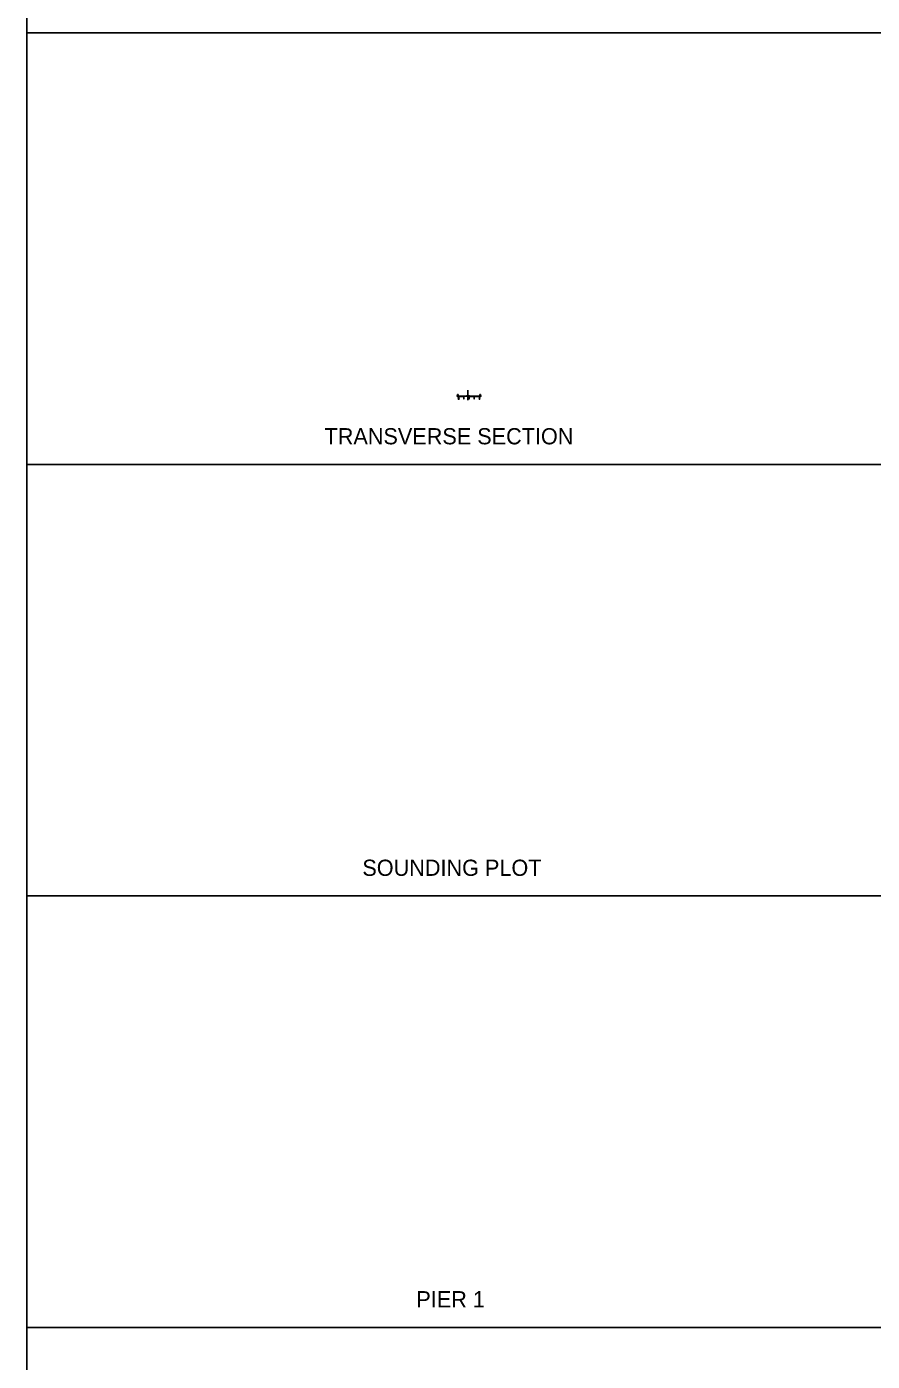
# Model space of a CAD drawing. Extents: x -6598 to 6602, y -3155 to 3145.
# Drawn here: x 3402 to 4970, y -818 to 1657 of the extents above; entities that cross this region are included whole.
import ezdxf

# ---------------------------------------------------------------- set-up
doc = ezdxf.new("R2010")
doc.units = 0
for name, color, linetype in [('BridgeExistingStructure', 7, 'Continuous'), ('PC_CONCRETE', 7, 'Continuous'), ('ShtPlotShapeBatchPrint', 7, 'Continuous')]:
    doc.layers.add(name, color=color, linetype=linetype)

msp = doc.modelspace()

# ---------------------------------------------------------------- linework, layer by layer
at = {"layer": 'BridgeExistingStructure'}
for p, q in [((4201.2, 973), (4200.1, 973)), ((4200.1, 973), (4200.1, 972)), ((4200.2, 971.9), (4200.1, 972)), ((4200.1, 971.9), (4200.1, 971.3)), ((4200.2, 971.9), (4200.1, 971.9)), ((4200.1, 971.3), (4200.3, 971.3)), ((4200.2, 971.9), (4201.8, 972)), ((4200.4, 971.3), (4200.3, 971.3)), ((4200.4, 971.3), (4200.4, 971.3)), ((4200.4, 971.3), (4201.9, 971.2)), ((4201.5, 974.9), (4200.7, 974.9)), ((4200.7, 974.9), (4200.7, 973)), ((4201.2, 973), (4201.7, 972.9)), ((4201.5, 974.9), (4201.5, 972.9)), ((4201.7, 972.9), (4201.8, 972.1)), ((4201.9, 971.3), (4201.9, 971.1)), ((4201.9, 971.3), (4203.2, 971.3)), ((4203.2, 971.2), (4201.9, 971.2)), ((4203.2, 971.1), (4201.9, 971.1)), ((4203.2, 966.7), (4201.9, 966.7)), ((4201.9, 966.5), (4201.9, 966.7)), ((4203.2, 966.6), (4201.9, 966.6)), ((4201.9, 966.5), (4203.2, 966.5)), ((4202.5, 966.7), (4202.5, 971.1)), ((4202.6, 966.7), (4202.6, 971.1)), ((4203.2, 971.3), (4211.5, 971.4)), ((4203.2, 971.3), (4203.2, 971.3)), ((4203.2, 971.3), (4203.2, 971.1)), ((4203.2, 966.5), (4203.2, 966.7)), ((4211.5, 971.4), (4211.5, 971.4)), ((4211.5, 971.4), (4211.5, 971.2)), ((4211.5, 971.4), (4212.8, 971.4)), ((4212.8, 971.3), (4211.5, 971.3)), ((4212.8, 971.2), (4211.5, 971.2)), ((4212.8, 966.9), (4211.5, 966.9)), ((4211.5, 966.7), (4211.5, 966.9)), ((4212.8, 966.8), (4211.5, 966.8)), ((4211.5, 966.7), (4212.8, 966.7)), ((4212.1, 966.9), (4212.1, 971.2)), ((4212.2, 966.9), (4212.2, 971.2)), ((4212.8, 971.5), (4219.8, 971.6)), ((4212.8, 971.4), (4212.8, 971.5)), ((4212.8, 971.4), (4212.8, 971.2)), ((4212.8, 966.7), (4212.8, 966.9)), ((4221.1, 971.6), (4219.8, 971.6)), ((4221.1, 971.5), (4221.1, 971.6)), ((4221.1, 971.5), (4221.1, 971.3)), ((4221.1, 971.5), (4222.5, 971.5)), ((4222.5, 971.4), (4221.1, 971.4)), ((4222.5, 971.3), (4221.1, 971.3)), ((4222.5, 967), (4221.1, 967)), ((4221.1, 966.8), (4221.1, 967)), ((4222.5, 966.9), (4221.1, 966.9)), ((4221.1, 966.8), (4222.5, 966.8)), ((4221.8, 967), (4221.8, 971.3)), ((4221.8, 967), (4221.8, 971.3)), ((4222.5, 971.5), (4222.5, 971.5)), ((4222.5, 971.5), (4222.5, 971.3)), ((4222.5, 966.8), (4222.5, 967)), ((4229.3, 972.1), (4233.8, 972)), ((4230.7, 971.4), (4230.7, 971.4)), ((4230.7, 971.4), (4230.7, 971.1)), ((4230.7, 971.4), (4232.1, 971.4)), ((4232.1, 971.3), (4230.7, 971.3)), ((4232.1, 971.1), (4230.7, 971.1)), ((4232.1, 966.8), (4230.7, 966.8)), ((4230.7, 966.6), (4230.7, 966.8)), ((4232.1, 966.7), (4230.7, 966.7)), ((4230.7, 966.6), (4232.1, 966.6)), ((4231.4, 966.8), (4231.4, 971.1)), ((4231.4, 966.8), (4231.4, 971.1)), ((4232.1, 971.4), (4232.1, 971.4)), ((4240.4, 971.3), (4232.1, 971.4)), ((4232.1, 971.4), (4232.1, 971.1)), ((4232.1, 966.6), (4232.1, 966.8)), ((4240.4, 971.2), (4240.4, 971.3)), ((4240.4, 971.2), (4240.4, 971)), ((4240.4, 971.2), (4241.7, 971.2)), ((4241.7, 971.1), (4240.4, 971.1)), ((4241.7, 971), (4240.4, 971)), ((4241.7, 966.7), (4240.4, 966.7)), ((4240.4, 966.5), (4240.4, 966.7)), ((4241.7, 966.6), (4240.4, 966.6)), ((4240.4, 966.5), (4241.7, 966.5)), ((4241, 966.7), (4241, 971)), ((4241.1, 966.7), (4241.1, 971)), ((4243.1, 971.2), (4241.7, 971.1)), ((4241.7, 971.2), (4241.7, 971)), ((4241.7, 966.5), (4241.7, 966.7)), ((4241.9, 972.9), (4241.8, 972)), ((4243.4, 971.9), (4241.8, 971.9)), ((4242.4, 972.9), (4241.9, 972.9)), ((4242.1, 974.9), (4243.2, 974.9)), ((4242.1, 974.9), (4242.1, 972.9)), ((4242.4, 972.9), (4243.5, 972.9)), ((4243.2, 971.3), (4243.1, 971.2)), ((4243.2, 974.9), (4243.2, 972.9)), ((4243.2, 971.3), (4243.3, 971.2)), ((4243.5, 971.2), (4243.3, 971.2)), ((4243.4, 971.9), (4243.5, 971.9)), ((4243.4, 971.9), (4243.5, 971.8)), ((4243.5, 972.9), (4243.5, 971.9)), ((4243.5, 971.8), (4243.5, 971.2))]:
    msp.add_line(p, q, dxfattribs=at)
for points in [[(4243.4, 971.9), (4243.5, 971.8), (4243.5, 971.2), (4243.3, 971.2), (4243.2, 971.3), (4243.1, 971.2), (4241.7, 971.1), (4241.7, 971.2), (4240.4, 971.2), (4240.4, 971.3), (4232.1, 971.4), (4232.1, 971.4), (4230.7, 971.4), (4230.7, 971.4), (4222.5, 971.5), (4222.5, 971.5), (4221.1, 971.5), (4221.1, 971.6), (4219.8, 971.6), (4212.8, 971.5), (4212.8, 971.4), (4211.5, 971.4), (4211.5, 971.4), (4203.2, 971.3), (4203.2, 971.3), (4201.9, 971.3), (4201.9, 971.2), (4200.4, 971.3), (4200.4, 971.3), (4200.3, 971.3), (4200.1, 971.3), (4200.1, 971.9), (4200.2, 971.9), (4201.8, 972), (4201.8, 971.9), (4216.8, 972.2), (4219.8, 972.2), (4222.8, 972.2), (4241.8, 971.9), (4241.8, 971.9)], [(4243.5, 972.9), (4243.5, 971.9), (4243.4, 971.9), (4241.8, 971.9), (4241.9, 972.9), (4242.4, 972.9)]]:
    msp.add_lwpolyline(points, close=True, dxfattribs=at)
msp.add_circle((4242.6, 972.4), 0.0833, dxfattribs=at)
at = {"layer": 'PC_CONCRETE'}
for p, q in [((4201.8, 972.1), (4216.8, 972.3)), ((4201.8, 971.9), (4216.8, 972.2)), ((4201.8, 972.1), (4201.8, 972)), ((4201.8, 972), (4201.8, 971.9)), ((4241.8, 972), (4222.8, 972.3)), ((4241.8, 971.9), (4222.8, 972.2)), ((4241.8, 972), (4241.8, 971.9)), ((4241.8, 971.9), (4241.8, 971.9))]:
    msp.add_line(p, q, dxfattribs=at)
msp.add_lwpolyline([(4241.8, 972), (4241.8, 971.9), (4241.8, 971.9), (4222.8, 972.2), (4219.8, 972.2), (4216.8, 972.2), (4201.8, 971.9), (4201.8, 972), (4201.8, 972.1)], dxfattribs=at)
for centre in [(4219.8, 672.3), (4219.8, 672.2)]:
    msp.add_arc(centre, 300, 89.427, 90.573, dxfattribs=at)
at = {"layer": 'ShtPlotShapeBatchPrint'}
msp.add_line((4219.8, 964.3), (4219.8, 982.8), dxfattribs=at)
for points in [[(3401.6, 3045.4), (6601.6, 3045.4), (6601.6, 1645.4), (3401.6, 1645.4)], [(3401.6, 1645.4), (5001.6, 1645.4), (5001.6, 845.4), (3401.6, 845.4)], [(3401.6, 845.4), (5001.6, 845.4), (5001.6, 45.4), (3401.6, 45.4)], [(3401.6, 45.4), (5001.6, 45.4), (5001.6, -754.6), (3401.6, -754.6)], [(3401.6, -754.6), (6601.6, -754.6), (6601.6, -1554.6), (3401.6, -1554.6)]]:
    msp.add_lwpolyline(points, close=True, dxfattribs=at)

# ---------------------------------------------------------------- texts
for s, p in [('TRANSVERSE SECTION', (3953.9, 882.5)), ('SOUNDING PLOT', (4024, 82.5)), ('PIER 1', (4124.1, -717.5))]:
    msp.add_text(s, height=30, dxfattribs=at).set_placement(p)

doc.saveas('drawing.dxf')
